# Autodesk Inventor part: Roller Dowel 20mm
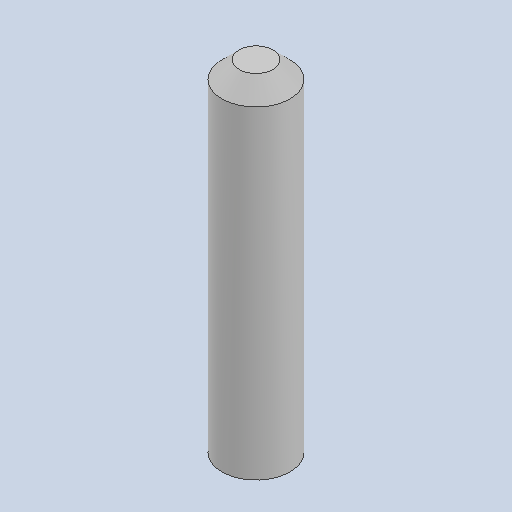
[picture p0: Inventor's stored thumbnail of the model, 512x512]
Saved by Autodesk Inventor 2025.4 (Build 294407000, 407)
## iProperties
Created: 2026-09
Part Number: Roller Dowel 20mm
Material: Generic
Document SubType Name: Modeling
Designer: AdminForWorker
Density: 1 g/cm^3
Appearance: Default
Title: Roller Dowel 20mm v1
Author: AdminForWorker
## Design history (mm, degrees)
feature "Body1"
body "Solid1"
